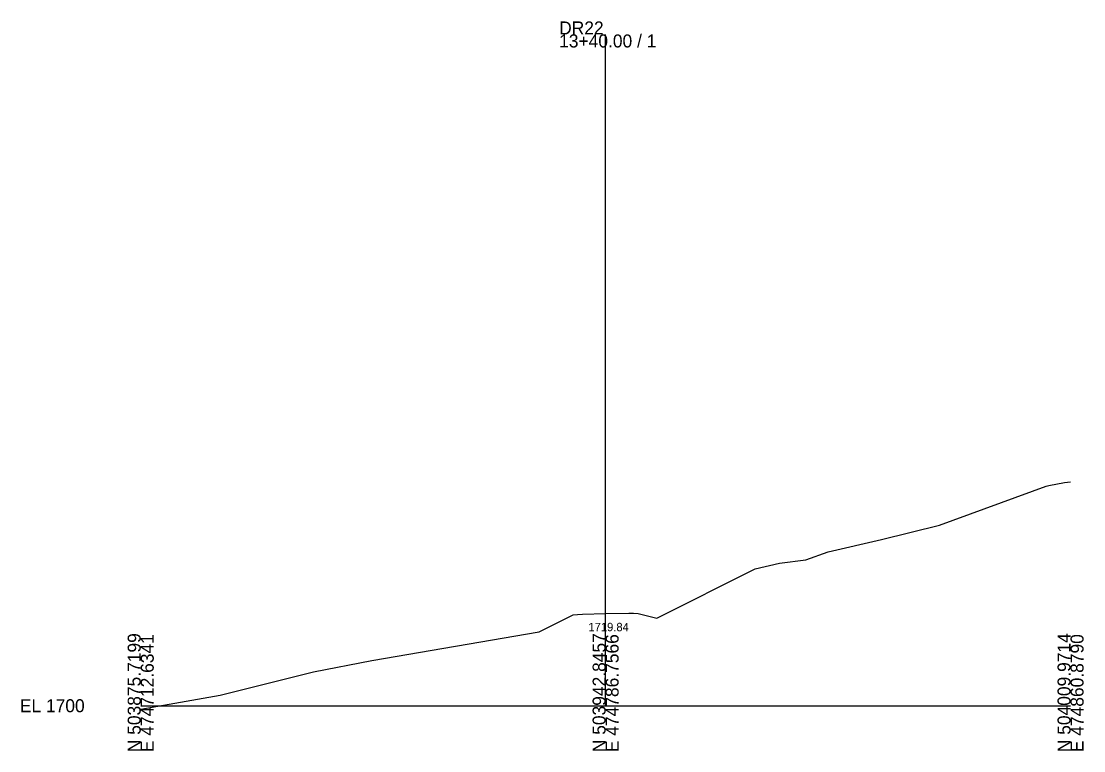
# Model space of a CAD drawing. Extents: x -26 to 1203, y -10 to 9633.
# Drawn here: x -25.7 to 202.8, y 8490.3 to 8647.3 of the extents above; entities that cross this region are included whole.
import ezdxf

# ---------------------------------------------------------------- set-up
doc = ezdxf.new("R2010")
doc.units = 0
for name, color, linetype in [('Exist Cross Section Cell', 7, 'Continuous'), ('Exist XS Center Line Elevation Label', 7, 'Continuous'), ('Exist XS Ground Line', 7, 'Continuous'), ('Scratch_Level_5', 7, 'Continuous')]:
    doc.layers.add(name, color=color, linetype=linetype)

msp = doc.modelspace()

# ---------------------------------------------------------------- linework, layer by layer
at = {"layer": 'Exist Cross Section Cell'}
for p, q in [((100, 8500), (100, 8644.48)), ((0, 8500), (100, 8500)), ((100, 8500), (200, 8500))]:
    msp.add_line(p, q, dxfattribs=at)
at = {"layer": 'Exist XS Ground Line'}
msp.add_lwpolyline([(0, 8499.28), (17.09, 8502.27), (37.14, 8507.29), (49.69, 8509.73), (85.7, 8515.93), (93, 8519.58), (93.98, 8519.66), (95, 8519.74), (100, 8519.84), (105, 8519.94), (106.02, 8519.9), (107, 8519.86), (111, 8518.86), (132.18, 8529.45), (137.38, 8530.65), (143.06, 8531.41), (147.85, 8533.12), (159.31, 8535.8), (171.8, 8538.85), (194.74, 8547.27), (195.34, 8547.38), (198.67, 8548.07), (200, 8548.16)], dxfattribs=at)
at = {"layer": 'Scratch_Level_5'}
msp.add_lwpolyline([(0, 8499.28), (17.09, 8502.27), (37.14, 8507.29), (49.69, 8509.73), (85.7, 8515.93), (93, 8519.58), (93.98, 8519.66), (95, 8519.74), (100, 8519.84), (105, 8519.94), (106.02, 8519.9), (107, 8519.86), (111, 8518.86), (132.18, 8529.45), (137.38, 8530.65), (143.06, 8531.41), (147.85, 8533.12), (159.31, 8535.8), (171.8, 8538.85), (194.74, 8547.27), (195.34, 8547.38), (198.67, 8548.07), (200, 8548.16)], dxfattribs=at)

# ---------------------------------------------------------------- texts
at = {"layer": 'Exist Cross Section Cell'}
for s, p in [('DR22', (90, 8644.48)), ('13+40.00 / 1', (90, 8641.68)), ('EL 1700', (-26, 8498.6))]:
    msp.add_text(s, height=2.8, dxfattribs=at).set_placement(p)
for s, p in [('N 503875.7199', (0, 8490)), ('E 474712.6341', (2.8, 8490)), ('N 503942.8457', (100, 8490)), ('E 474786.7566', (102.8, 8490)), ('N 504009.9714', (200, 8490)), ('E 474860.8790', (202.8, 8490))]:
    msp.add_text(s, height=2.8, rotation=90, dxfattribs=at).set_placement(p)
at = {"layer": 'Exist XS Center Line Elevation Label'}
msp.add_text('1719.84', height=1.8, dxfattribs=at).set_placement((96.29, 8516.04))

doc.saveas('drawing.dxf')
